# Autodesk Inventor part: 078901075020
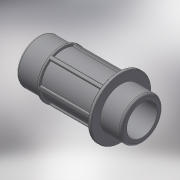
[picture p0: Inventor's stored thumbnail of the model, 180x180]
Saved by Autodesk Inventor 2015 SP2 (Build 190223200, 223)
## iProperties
Created: 2018-02
Part Number: 078901075020
Material: Generic
Description: PLASSON THREADED MALE ADAPTOR 75-2"
Document SubType Name: Modeling
Designer: KIM
Density: 1 g/cm^3
Appearance: Default
Author: KIM
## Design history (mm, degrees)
derived "078901.ipt"
feature "Solid1::078901.ipt"
tag "TaggingFeature1"
body "Solid1"
other parameters: "d4" = 2.9807, "d14" = 4.76912, "d15" = 2.38456, "d17" = 0, "d20" = 360 deg, "d40" = 26, "d41" = 59.614, "d45" = 65.5754, "d46" = 41.7298, "d47" = 2.6, "d77" = 132, "d78" = 75, "d85" = 0.59614, "d91" = 26.4, "d103" = 30.36, "d105" = 0.59614, "R_" = 59.614, "l_2" = 26, "l_" = 132, "d_" = 75
